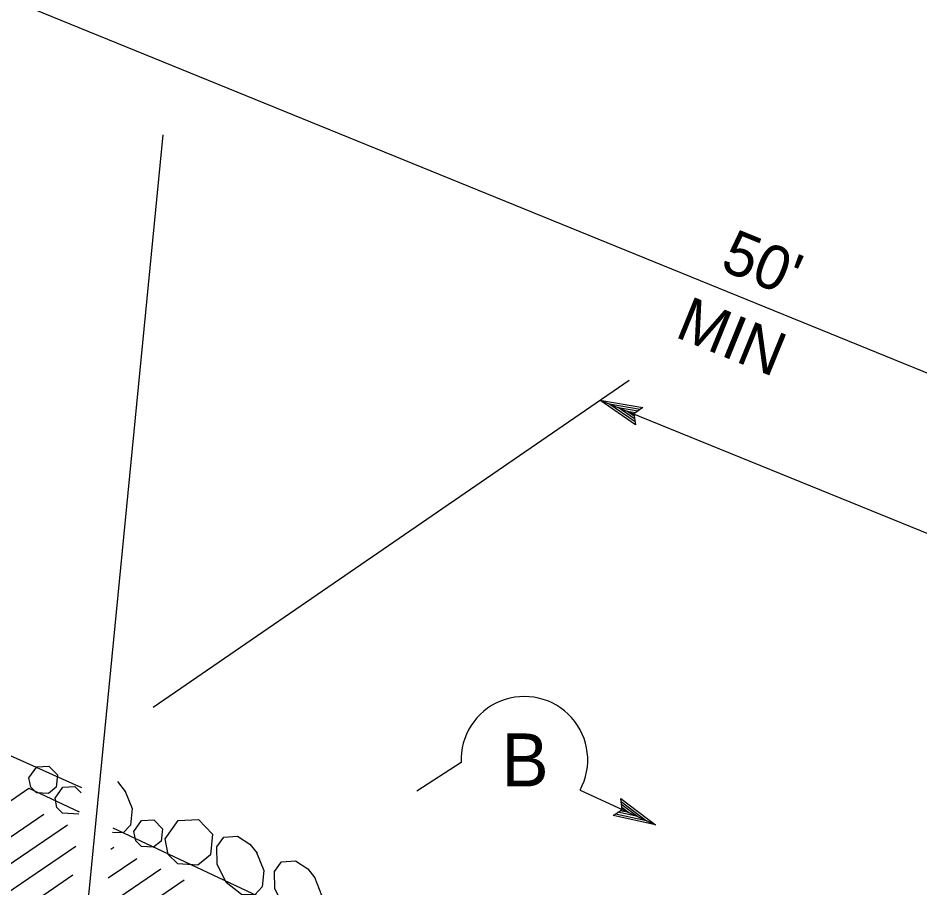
# Model space of a CAD drawing. Extents: x 6709491 to 6710959, y 1869789 to 1870763.
# Drawn here: x 6709921 to 6710043.7, y 1870319.2 to 1870437.5 of the extents above; entities that cross this region are included whole.
import ezdxf

# ---------------------------------------------------------------- set-up
doc = ezdxf.new("R2010")
doc.units = 0
for name, color, linetype in [('56 Stg 3 Anno', 7, 'Continuous'), ('57 Undefined', 7, 'Continuous'), ('60 Nongeo Data', 7, 'Continuous')]:
    doc.layers.add(name, color=color, linetype=linetype)

msp = doc.modelspace()

# ---------------------------------------------------------------- linework, layer by layer
at = {"layer": '56 Stg 3 Anno'}
for p, q in [((6709859.63, 1870464.61), (6710181.3, 1870333.54)), ((6709929.11, 1870303.2), (6709940.74, 1870421.63)), ((6709939.36, 1870343.76), (6710004.11, 1870388.26)), ((6710000.15, 1870385.54), (6710160.97, 1870320.01)), ((6710005, 1870382.18), (6710000.15, 1870385.54)), ((6710000.15, 1870385.54), (6710000.15, 1870385.54)), ((6710000.15, 1870385.54), (6710005.97, 1870384.55)), ((6710004.94, 1870382.57), (6710001.38, 1870385.04)), ((6710001.39, 1870385.04), (6710005.63, 1870384.32)), ((6710004.86, 1870382.98), (6710002.61, 1870384.54)), ((6710002.61, 1870384.54), (6710005.34, 1870384.07)), ((6710004.83, 1870383.35), (6710003.83, 1870384.04)), ((6710003.83, 1870384.04), (6710005.01, 1870383.84)), ((6710005.97, 1870384.55), (6710004.77, 1870383.66)), ((6710005.97, 1870384.55), (6710005.97, 1870384.55)), ((6710004.77, 1870383.66), (6710005, 1870382.18)), ((6710005, 1870382.18), (6710005, 1870382.18)), ((6709981.27, 1870336.23), (6709975.24, 1870332.35)), ((6709997.45, 1870332.49), (6710007.7, 1870327.76)), ((6710003.16, 1870329.85), (6710003, 1870331.35)), ((6710003, 1870331.35), (6710003, 1870331.35)), ((6710003, 1870331.35), (6710007.7, 1870327.76)), ((6710003.05, 1870330.95), (6710006.5, 1870328.32)), ((6710001.93, 1870329.02), (6710003.16, 1870329.85)), ((6710003.11, 1870330.54), (6710005.29, 1870328.88)), ((6710003.12, 1870330.17), (6710004.08, 1870329.43)), ((6710007.7, 1870327.76), (6710001.93, 1870329.02)), ((6710001.93, 1870329.02), (6710001.93, 1870329.02)), ((6710006.48, 1870328.32), (6710002.28, 1870329.23)), ((6710005.29, 1870328.88), (6710002.57, 1870329.47)), ((6710004.08, 1870329.43), (6710002.92, 1870329.68)), ((6710007.7, 1870327.76), (6710007.7, 1870327.76))]:
    msp.add_line(p, q, dxfattribs=at)
msp.add_arc((6709989.87, 1870336.6), 8.62, 331.4936, 182.464, dxfattribs=at)
at = {"layer": '60 Nongeo Data'}
for p, q in [((6709846.99, 1870369.89), (6709929.61, 1870332.83)), ((6709845.05, 1870279.98), (6709922.46, 1870332.74)), ((6709922.46, 1870332.74), (6709929.28, 1870329.53)), ((6709851.95, 1870279.8), (6709924.47, 1870329.23)), ((6709855.14, 1870278.31), (6709927.7, 1870327.77)), ((6709933.89, 1870327.37), (6709972.77, 1870309.11)), ((6709858.32, 1870276.81), (6709928.82, 1870324.87)), ((6709933.61, 1870324.47), (6709934.01, 1870324.74)), ((6709933.22, 1870320.54), (6709937.12, 1870323.2)), ((6709932.84, 1870316.62), (6709940.39, 1870321.77)), ((6709861.5, 1870275.32), (6709928.44, 1870320.94)), ((6709932.45, 1870312.69), (6709943.58, 1870320.28))]:
    msp.add_line(p, q, dxfattribs=at)
for points in [[(6709922.46, 1870334.17), (6709923.51, 1870335.66), (6709925.17, 1870335.75), (6709926.33, 1870334.55), (6709926.16, 1870332.87), (6709925.13, 1870332.01), (6709923.49, 1870332.13), (6709922.71, 1870332.88), (6709922.46, 1870334.17)], [(6709934.51, 1870333.65), (6709935.57, 1870332.32)], [(6709926, 1870331.41), (6709927.05, 1870332.89), (6709928.71, 1870332.99), (6709929.54, 1870332.13)], [(6709935.51, 1870332.42), (6709936.48, 1870329.98), (6709936.28, 1870327.74), (6709935.27, 1870326.67), (6709933.83, 1870326.7)], [(6709929.25, 1870329.2), (6709927.03, 1870329.36), (6709926.26, 1870330.12), (6709926.01, 1870331.41)], [(6709941, 1870325.86), (6709942.74, 1870328.34), (6709945.52, 1870328.5), (6709947.45, 1870326.49), (6709947.17, 1870323.69), (6709945.45, 1870322.26), (6709942.71, 1870322.46), (6709941.42, 1870323.71), (6709941, 1870325.86)], [(6709936.74, 1870326.87), (6709937.78, 1870328.35), (6709939.45, 1870328.45), (6709940.61, 1870327.24), (6709940.44, 1870325.56), (6709939.41, 1870324.71), (6709937.77, 1870324.82), (6709936.99, 1870325.58), (6709936.74, 1870326.87)], [(6709953.44, 1870324), (6709954.41, 1870321.56), (6709954.21, 1870319.32), (6709953.2, 1870318.26), (6709951.38, 1870318.29), (6709949.31, 1870319.91), (6709948.07, 1870322.41), (6709948.02, 1870324.76), (6709948.97, 1870326.09), (6709950.84, 1870326.21), (6709952.52, 1870325.14), (6709953.5, 1870323.91)], [(6709961.31, 1870320.65), (6709962.27, 1870318.21), (6709962.08, 1870315.97), (6709961.07, 1870314.91), (6709959.25, 1870314.94), (6709957.18, 1870316.56), (6709955.93, 1870319.06), (6709955.89, 1870321.41), (6709956.83, 1870322.74), (6709958.71, 1870322.86), (6709960.39, 1870321.79), (6709961.37, 1870320.56)]]:
    msp.add_lwpolyline(points, dxfattribs=at)

# ---------------------------------------------------------------- texts
at = {"layer": '57 Undefined'}
for s, p in [("50'", (6710016.32, 1870403.36)), ('MIN', (6710010.18, 1870394.2))]:
    msp.add_text(s, height=6, rotation=337.8294, dxfattribs=at).set_placement(p)
msp.add_text('B', height=7.21, dxfattribs=at).set_placement((6709986.74, 1870332.99))

doc.saveas('drawing.dxf')
